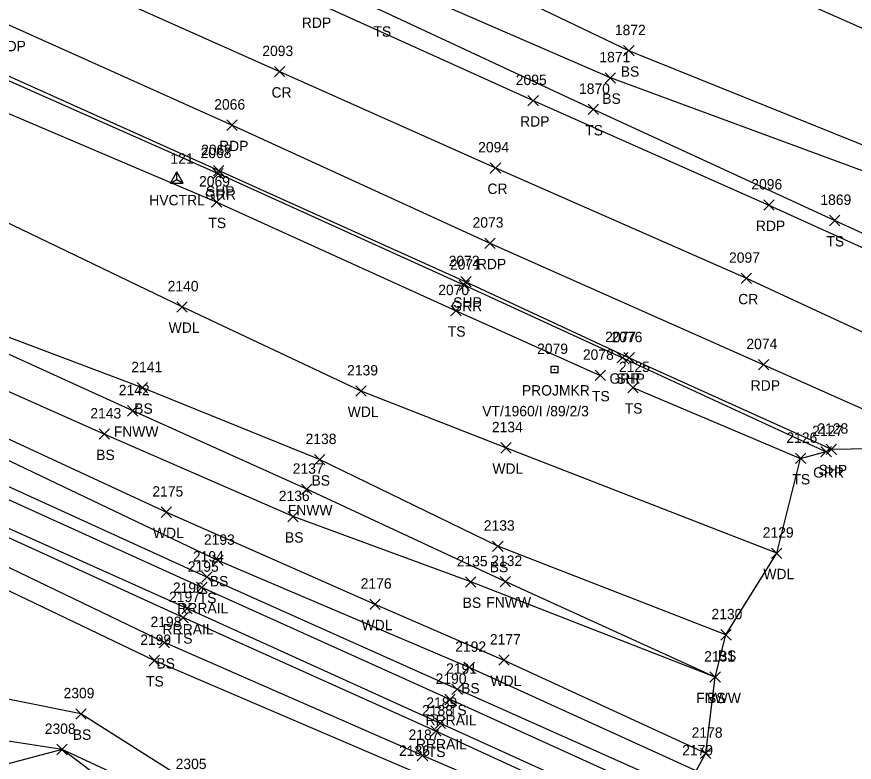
# Model space of a CAD drawing. Extents: x 1599569 to 1610055, y 642560 to 647860.
# Drawn here: x 1601651.7 to 1601812.9, y 647061.1 to 647204.6 of the extents above; entities that cross this region are included whole.
import ezdxf

# ---------------------------------------------------------------- set-up
doc = ezdxf.new("R2010")
doc.units = 0
for name, color, linetype in [('C_A', 7, 'Continuous'), ('C_I', 7, 'Continuous'), ('CPSM', 7, 'Continuous'), ('L_A', 7, 'Continuous'), ('L_I', 7, 'Continuous'), ('L_TIC', 7, 'Continuous'), ('LAWA', 7, 'Continuous'), ('LELB', 7, 'Continuous'), ('LFNC', 7, 'Continuous'), ('LSOGP', 7, 'Continuous'), ('P_A', 7, 'Continuous'), ('P_I', 7, 'Continuous'), ('P_TIC', 7, 'Continuous'), ('PET', 7, 'Continuous'), ('PRC', 7, 'Continuous'), ('PSP', 7, 'Continuous'), ('R_A', 7, 'Continuous'), ('R_I', 7, 'Continuous'), ('R_TIC', 7, 'Continuous'), ('RGR', 7, 'Continuous'), ('RR', 7, 'Continuous'), ('S_A', 7, 'Continuous'), ('S_C', 7, 'Continuous'), ('S_I', 7, 'Continuous'), ('SRM', 7, 'Continuous')]:
    doc.layers.add(name, color=color, linetype=linetype)

msp = doc.modelspace()

# ---------------------------------------------------------------- linework, layer by layer
at = {"layer": 'CPSM'}
for p, q in [((1601681.25, 647172.55), (1601682.5, 647174.72)), ((1601681.25, 647172.55), (1601682.5, 647173.27)), ((1601683.75, 647172.55), (1601682.5, 647174.72)), ((1601682.5, 647173.27), (1601682.5, 647174.72)), ((1601682.5, 647173.27), (1601682.5, 647173.27)), ((1601682.5, 647173.27), (1601683.75, 647172.55)), ((1601681.25, 647172.55), (1601683.75, 647172.55))]:
    msp.add_line(p, q, dxfattribs=at)
at = {"layer": 'L_TIC'}
for points in [[(1601768.5, 647197.02), (1601770.5, 647199.02)], [(1601770.5, 647197.02), (1601768.5, 647199.02)], [(1601764.95, 647191.8), (1601766.95, 647193.8)], [(1601766.95, 647191.8), (1601764.95, 647193.8)], [(1601761.69, 647185.72), (1601763.69, 647187.72)], [(1601763.69, 647185.72), (1601761.69, 647187.72)], [(1601689.17, 647167.89), (1601691.17, 647169.89)], [(1601691.17, 647167.89), (1601689.17, 647169.89)], [(1601808.11, 647164.35), (1601810.11, 647166.35)], [(1601810.11, 647164.35), (1601808.11, 647166.35)], [(1601682.51, 647147.72), (1601684.51, 647149.72)], [(1601684.51, 647147.72), (1601682.51, 647149.72)], [(1601735.24, 647146.99), (1601737.24, 647148.99)], [(1601737.24, 647146.99), (1601735.24, 647148.99)], [(1601762.99, 647134.54), (1601764.99, 647136.54)], [(1601764.99, 647134.54), (1601762.99, 647136.54)], [(1601674.86, 647132.15), (1601676.86, 647134.15)], [(1601676.86, 647132.15), (1601674.86, 647134.15)], [(1601716.97, 647131.53), (1601718.97, 647133.53)], [(1601718.97, 647131.53), (1601716.97, 647133.53)], [(1601769.29, 647132.19), (1601771.29, 647134.19)], [(1601771.29, 647132.19), (1601769.29, 647134.19)], [(1601673.01, 647127.72), (1601675.01, 647129.72)], [(1601675.01, 647127.72), (1601673.01, 647129.72)], [(1601667.54, 647123.24), (1601669.54, 647125.24)], [(1601669.54, 647123.24), (1601667.54, 647125.24)], [(1601744.83, 647120.59), (1601746.83, 647122.59)], [(1601746.83, 647120.59), (1601744.83, 647122.59)], [(1601708.97, 647118.32), (1601710.97, 647120.32)], [(1601710.97, 647118.32), (1601708.97, 647120.32)], [(1601801.57, 647118.55), (1601803.57, 647120.55)], [(1601803.57, 647118.55), (1601801.57, 647120.55)], [(1601706.5, 647112.61), (1601708.5, 647114.61)], [(1601708.5, 647112.61), (1601706.5, 647114.61)], [(1601679.48, 647108.21), (1601681.48, 647110.21)], [(1601681.48, 647108.21), (1601679.48, 647110.21)], [(1601703.87, 647107.35), (1601705.87, 647109.35)], [(1601705.87, 647107.35), (1601703.87, 647109.35)], [(1601743.28, 647101.65), (1601745.28, 647103.65)], [(1601745.28, 647101.65), (1601743.28, 647103.65)], [(1601689.4, 647098.93), (1601691.4, 647100.93)], [(1601691.4, 647098.93), (1601689.4, 647100.93)], [(1601796.97, 647100.31), (1601798.97, 647102.31)], [(1601798.97, 647100.31), (1601796.97, 647102.31)], [(1601687.29, 647095.71), (1601689.29, 647097.71)], [(1601689.29, 647095.71), (1601687.29, 647097.71)], [(1601738.06, 647094.78), (1601740.06, 647096.78)], [(1601740.06, 647094.78), (1601738.06, 647096.78)], [(1601744.72, 647094.86), (1601746.72, 647096.86)], [(1601746.72, 647094.86), (1601744.72, 647096.86)], [(1601719.64, 647090.49), (1601721.64, 647092.49)], [(1601721.64, 647090.49), (1601719.64, 647092.49)], [(1601682.7, 647087.91), (1601684.7, 647089.91)], [(1601684.7, 647087.91), (1601682.7, 647089.91)], [(1601787.18, 647084.6), (1601789.18, 647086.6)], [(1601789.18, 647084.6), (1601787.18, 647086.6)], [(1601679.12, 647083.11), (1601681.12, 647085.11)], [(1601681.12, 647083.11), (1601679.12, 647085.11)], [(1601677.16, 647079.66), (1601679.16, 647081.66)], [(1601679.16, 647079.66), (1601677.16, 647081.66)], [(1601744.45, 647079.74), (1601746.45, 647081.74)], [(1601746.45, 647079.74), (1601744.45, 647081.74)], [(1601737.77, 647078.33), (1601739.77, 647080.33)], [(1601739.77, 647078.33), (1601737.77, 647080.33)], [(1601785.11, 647076.46), (1601787.11, 647078.46)], [(1601787.11, 647076.46), (1601785.11, 647078.46)], [(1601785.11, 647076.46), (1601787.11, 647078.46)], [(1601787.11, 647076.46), (1601785.11, 647078.46)], [(1601735.46, 647074.12), (1601737.46, 647076.12)], [(1601737.46, 647074.12), (1601735.46, 647076.12)], [(1601663.03, 647069.39), (1601665.03, 647071.39)], [(1601665.03, 647069.39), (1601663.03, 647071.39)], [(1601731.38, 647066.08), (1601733.38, 647068.08)], [(1601733.38, 647066.08), (1601731.38, 647068.08)], [(1601659.42, 647062.53), (1601661.42, 647064.53)], [(1601661.42, 647062.53), (1601659.42, 647064.53)], [(1601659.42, 647062.53), (1601661.42, 647064.53)], [(1601661.42, 647062.53), (1601659.42, 647064.53)], [(1601783.29, 647061.8), (1601785.29, 647063.8)], [(1601785.29, 647061.8), (1601783.29, 647063.8)], [(1601728.79, 647061.38), (1601730.79, 647063.38)], [(1601730.79, 647061.38), (1601728.79, 647063.38)]]:
    msp.add_lwpolyline(points, dxfattribs=at)
at = {"layer": 'LAWA'}
for points in [[(1601797.97, 647101.31), (1601745.83, 647121.59), (1601717.97, 647132.53), (1601683.51, 647148.72), (1601645.76, 647166.92), (1601608.71, 647184.55), (1601562.01, 647202.4), (1601544.62, 647197.58)], [(1601522.66, 647190.03), (1601554.72, 647173.2), (1601590.69, 647150.24), (1601642.66, 647126.73), (1601680.48, 647109.21), (1601720.64, 647091.49), (1601745.45, 647080.74), (1601784.29, 647062.8)]]:
    msp.add_lwpolyline(points, dxfattribs=at)
at = {"layer": 'LELB'}
for points in [[(1601962.97, 647113.31), (1601923.69, 647130.08), (1601895.55, 647143.8), (1601852.73, 647162.89), (1601817.77, 647178.58), (1601769.5, 647198.02), (1601730.98, 647216.5), (1601688.1, 647233.1), (1601653.57, 647246.64), (1601608.27, 647265.53), (1601581.18, 647285.19)], [(1601782.46, 647059.4), (1601738.77, 647079.33), (1601690.4, 647099.93), (1601647.7, 647120.25), (1601610.06, 647137.74), (1601571.92, 647154.07), (1601536.97, 647170.25), (1601497.74, 647186.59), (1601465.75, 647201.27), (1601394.71, 647231.37), (1601362.21, 647245.73), (1601329.86, 647260.18), (1601292.61, 647278.06)], [(1601646.77, 647277.53), (1601686.47, 647261.15), (1601728.27, 647241.55), (1601783.31, 647216.16), (1601831.6, 647194.79), (1601880.63, 647172.23), (1601925.63, 647152.36), (1601972.37, 647131.79)], [(1601779.91, 647055.75), (1601736.46, 647075.12), (1601688.29, 647096.71), (1601645.48, 647116.21), (1601608.08, 647132.73), (1601569.65, 647149.89), (1601535.69, 647165.81), (1601496.65, 647183.57), (1601464.02, 647197.75), (1601393.37, 647229.99), (1601361.18, 647244.46), (1601329.08, 647258.95), (1601292.39, 647275.61)], [(1601775.59, 647047.17), (1601732.38, 647067.08), (1601683.7, 647088.91), (1601643.36, 647107.34), (1601603.44, 647124.91), (1601567.99, 647141.64), (1601531.27, 647157.66), (1601493.8, 647174.33), (1601459.44, 647189.9), (1601386.61, 647223.07), (1601358.08, 647235.63), (1601326.17, 647250.65), (1601291.06, 647266.1)], [(1601955.14, 647100.52), (1601918.75, 647116.38), (1601885.72, 647130.9), (1601846.21, 647148.37), (1601809.11, 647165.35), (1601762.69, 647186.72), (1601721.93, 647205.72), (1601682.69, 647222.55), (1601645.99, 647239.88), (1601604.12, 647258.19), (1601590.91, 647265.16)], [(1601773.31, 647043.55), (1601729.79, 647062.38), (1601680.12, 647084.11), (1601641.71, 647102.62), (1601602.29, 647120.48), (1601566.23, 647136.75), (1601528.31, 647153.55), (1601493.2, 647170.67), (1601457.65, 647186.55), (1601384.33, 647220.55), (1601356.62, 647233.9), (1601324.87, 647247.72), (1601290.33, 647262.4)], [(1601508.71, 647251.5), (1601538.21, 647237.23), (1601574.14, 647220.89), (1601606.18, 647207.34), (1601643.43, 647188.75), (1601690.17, 647168.89), (1601736.24, 647147.99), (1601763.99, 647135.54)], [(1601961.31, 647109.79), (1601923.17, 647125.81), (1601892.78, 647139.96), (1601850.81, 647159.82), (1601815.66, 647174.43), (1601765.95, 647192.8), (1601725.86, 647210.28), (1601688.1, 647233.1)], [(1601788.18, 647085.6), (1601744.28, 647102.65), (1601709.97, 647119.32), (1601675.86, 647133.15), (1601636.27, 647148.1), (1601596.45, 647168.4), (1601558.79, 647183.8), (1601537.2, 647194.37)], [(1601786.11, 647077.46), (1601739.06, 647095.78), (1601704.87, 647108.35), (1601668.54, 647124.24), (1601631.14, 647140.81), (1601590.66, 647159.56), (1601563.92, 647171), (1601557.22, 647179.13)], [(1601751.67, 647030.89), (1601730.47, 647037.42), (1601697.62, 647051.94), (1601683.46, 647052.81), (1601660.42, 647063.53), (1601634.93, 647067.43), (1601609.86, 647081.03), (1601579.64, 647095.5), (1601544.78, 647095.79), (1601527.55, 647075.32), (1601502.18, 647078.34), (1601460.45, 647090.07), (1601427.5, 647095.12), (1601380.72, 647086.4), (1601347.8, 647085.38), (1601322.34, 647094.84), (1601293.67, 647118.34), (1601268.03, 647147.72), (1601257.75, 647175.7)], [(1601786.42, 647020.74), (1601762.67, 647028.99), (1601751.67, 647030.89), (1601732.96, 647040.23), (1601698.47, 647053.93), (1601685.61, 647056.76), (1601664.03, 647070.39), (1601639.36, 647075.33), (1601612.31, 647092.93), (1601584.19, 647104.61), (1601538.73, 647126.26), (1601520.13, 647131.26), (1601491.52, 647137.58), (1601474.1, 647124.14), (1601450.02, 647123.17), (1601433.67, 647131.14), (1601416.15, 647122.17), (1601393.03, 647131.84), (1601363.94, 647128.32), (1601336.7, 647135.49), (1601311.97, 647149.61), (1601287.9, 647169.52)], [(1601770.94, 647039.49), (1601728.02, 647059.31), (1601678.16, 647080.66), (1601639.64, 647099.09), (1601600.86, 647116.76), (1601564.63, 647133.02), (1601543.96, 647141.4)], [(1601770.29, 647133.19), (1601802.57, 647119.55)], [(1601762.67, 647028.99), (1601750.87, 647021.59), (1601728.34, 647036), (1601697.16, 647048.99), (1601679.27, 647049.33), (1601660.42, 647063.53), (1601632.57, 647056.16), (1601605.11, 647066.7), (1601577.38, 647081.92), (1601557.99, 647089.73)]]:
    msp.add_lwpolyline(points, dxfattribs=at)
at = {"layer": 'LFNC'}
msp.add_lwpolyline([(1601786.11, 647077.46), (1601745.72, 647095.86), (1601707.5, 647113.61), (1601674.01, 647128.72), (1601634.94, 647146.46), (1601593.54, 647164.14), (1601557.22, 647179.13), (1601524.27, 647193.83)], dxfattribs=at)
at = {"layer": 'LSOGP'}
msp.add_lwpolyline([(1601782.46, 647059.4), (1601784.29, 647062.81), (1601786.11, 647077.47), (1601788.18, 647085.61), (1601797.97, 647101.31), (1601802.57, 647119.55), (1601807.48, 647120.86), (1601808.48, 647121.33), (1601831.12, 647121.72), (1601838.26, 647118.54), (1601845.39, 647115.36), (1601852.52, 647112.19), (1601874.76, 647116.71), (1601912.89, 647115.64), (1601955.15, 647100.52)], dxfattribs=at)
at = {"layer": 'P_TIC'}
for points in [[(1601701.28, 647193), (1601703.28, 647195)], [(1601703.28, 647193), (1601701.28, 647195)], [(1601750.08, 647187.42), (1601752.08, 647189.42)], [(1601752.08, 647187.42), (1601750.08, 647189.42)], [(1601692.14, 647182.7), (1601694.14, 647184.7)], [(1601694.14, 647182.7), (1601692.14, 647184.7)], [(1601689.56, 647173.95), (1601691.56, 647175.95)], [(1601691.56, 647173.95), (1601689.56, 647175.95)], [(1601742.84, 647174.46), (1601744.84, 647176.46)], [(1601744.84, 647174.46), (1601742.84, 647176.46)], [(1601795.47, 647167.32), (1601797.47, 647169.32)], [(1601797.47, 647167.32), (1601795.47, 647169.32)], [(1601741.76, 647159.97), (1601743.76, 647161.97)], [(1601743.76, 647159.97), (1601741.76, 647161.97)], [(1601737.15, 647152.57), (1601739.15, 647154.57)], [(1601739.15, 647152.57), (1601737.15, 647154.57)], [(1601791.12, 647153.22), (1601793.12, 647155.22)], [(1601793.12, 647153.22), (1601791.12, 647155.22)], [(1601768.56, 647137.92), (1601770.56, 647139.92)], [(1601770.56, 647137.92), (1601768.56, 647139.92)], [(1601794.46, 647136.6), (1601796.46, 647138.6)], [(1601796.46, 647136.6), (1601794.46, 647138.6)], [(1601807.48, 647120.32), (1601809.48, 647122.32)], [(1601809.48, 647120.32), (1601807.48, 647122.32)]]:
    msp.add_lwpolyline(points, dxfattribs=at)
at = {"layer": 'PET'}
for points in [[(1601331.98, 647346.68), (1601356.59, 647335.73), (1601398.36, 647316.98), (1601437.48, 647298.89), (1601470.99, 647284.11), (1601510.02, 647266.15), (1601543.75, 647251.34), (1601580.52, 647234.21), (1601606.39, 647222.8), (1601650.31, 647202.92), (1601693.14, 647183.7), (1601742.76, 647160.97), (1601795.46, 647137.6), (1601852.51, 647112.19)], [(1601401.84, 647345.99), (1601436.76, 647329.85), (1601477.89, 647310.69), (1601511.69, 647295.64), (1601529.2, 647287.58), (1601568.21, 647270.13), (1601613.57, 647249.46), (1601666.31, 647226.36), (1601709.07, 647207.41), (1601751.08, 647188.42), (1601796.47, 647168.32), (1601839.63, 647148.76), (1601881.89, 647129.58), (1601912.89, 647115.63)]]:
    msp.add_lwpolyline(points, dxfattribs=at)
at = {"layer": 'PRC'}
msp.add_lwpolyline([(1601345.39, 647355.71), (1601383.98, 647338.31), (1601428.29, 647317.74), (1601472.83, 647297.09), (1601504.71, 647281.99), (1601534.71, 647269.01), (1601561.28, 647257.19), (1601605.65, 647237.34), (1601658.4, 647213.63), (1601702.28, 647194), (1601743.84, 647175.46), (1601792.12, 647154.22), (1601833.09, 647135.23), (1601874.76, 647116.71)], dxfattribs=at)
at = {"layer": 'PSP'}
msp.add_lwpolyline([(1601320.4, 647342.24), (1601352.25, 647327.85), (1601395.49, 647308.51), (1601432.16, 647291.56), (1601467.04, 647275.92), (1601506.79, 647257.96), (1601540.92, 647242.41), (1601577, 647226.25), (1601607.65, 647212.12), (1601646.7, 647194.68), (1601690.56, 647174.95), (1601738.15, 647153.57), (1601769.56, 647138.92), (1601808.48, 647121.32)], dxfattribs=at)
at = {"layer": 'R_TIC'}
for points in [[(1601689.44, 647173.37), (1601691.44, 647175.37)], [(1601691.44, 647173.37), (1601689.44, 647175.37)], [(1601736.84, 647151.88), (1601738.84, 647153.88)], [(1601738.84, 647151.88), (1601736.84, 647153.88)], [(1601767.28, 647137.94), (1601769.28, 647139.94)], [(1601769.28, 647137.94), (1601767.28, 647139.94)], [(1601806.48, 647119.85), (1601808.48, 647121.85)], [(1601808.48, 647119.85), (1601806.48, 647121.85)], [(1601686.31, 647093.74), (1601688.31, 647095.74)], [(1601688.31, 647093.74), (1601686.31, 647095.74)], [(1601683.48, 647089.67), (1601685.48, 647091.67)], [(1601685.48, 647089.67), (1601683.48, 647091.67)], [(1601734.09, 647072.16), (1601736.09, 647074.16)], [(1601736.09, 647072.16), (1601734.09, 647074.16)], [(1601732.22, 647067.55), (1601734.22, 647069.55)], [(1601734.22, 647067.55), (1601732.22, 647069.55)]]:
    msp.add_lwpolyline(points, dxfattribs=at)
at = {"layer": 'RGR'}
msp.add_lwpolyline([(1601318.76, 647342.22), (1601351.89, 647327.35), (1601395.14, 647307.81), (1601432.06, 647291.1), (1601467.03, 647275.18), (1601506.65, 647256.87), (1601540.97, 647241.89), (1601576.91, 647225.43), (1601607.45, 647211.71), (1601646.25, 647193.96), (1601690.44, 647174.37), (1601737.84, 647152.88), (1601768.28, 647138.94), (1601807.48, 647120.85)], dxfattribs=at)
at = {"layer": 'RR'}
for points in [[(1601779.12, 647053.17), (1601735.09, 647073.16), (1601687.31, 647094.74), (1601644.71, 647114), (1601606.95, 647130.88), (1601569.09, 647148.12), (1601534.47, 647163.75), (1601495.86, 647181.28), (1601463.02, 647196.09), (1601391.8, 647228.12), (1601360.22, 647242.53), (1601328.26, 647256.93), (1601292.48, 647273.14)], [(1601776.78, 647048.8), (1601733.22, 647068.55), (1601684.48, 647090.67), (1601642.81, 647109.31), (1601604.47, 647126.66), (1601567.91, 647143.17), (1601532.13, 647159.27), (1601494.47, 647176.35), (1601460.57, 647191.75), (1601388.17, 647224.38), (1601357.5, 647238.3), (1601326.5, 647252.29), (1601291.28, 647268.22)]]:
    msp.add_lwpolyline(points, dxfattribs=at)
at = {"layer": 'SRM'}
msp.add_lwpolyline([(1601754.56, 647137.28), (1601755.81, 647137.28), (1601755.81, 647136.03), (1601754.56, 647136.03)], close=True, dxfattribs=at)
msp.add_circle((1601755.19, 647136.66), 0.0833, dxfattribs=at)

# ---------------------------------------------------------------- texts
at = {"layer": 'C_A'}
msp.add_text('HVCTRL', height=2, dxfattribs=at).set_placement((1601677.19, 647168.27))
at = {"layer": 'C_I'}
msp.add_text('121', height=2, dxfattribs=at).set_placement((1601681.27, 647176.27))
at = {"layer": 'L_A'}
for s, p in [('TS', (1601720.34, 647200.72)), ('BS', (1601767.94, 647193.02)), ('BS', (1601764.39, 647187.8)), ('TS', (1601761.1, 647181.72)), ('TS', (1601688.57, 647163.89)), ('TS', (1601807.52, 647160.35)), ('WDL', (1601680.93, 647143.72)), ('TS', (1601734.65, 647142.99)), ('TS', (1601762.4, 647130.54)), ('BS', (1601674.3, 647128.15)), ('TS', (1601768.7, 647128.19)), ('WDL', (1601715.39, 647127.53)), ('FNWW', (1601670.36, 647123.72)), ('BS', (1601666.98, 647119.24)), ('WDL', (1601743.24, 647116.59)), ('BS', (1601708.41, 647114.32)), ('TS', (1601800.98, 647114.55)), ('FNWW', (1601703.85, 647108.61)), ('WDL', (1601677.9, 647104.21)), ('BS', (1601703.31, 647103.35)), ('BS', (1601742.72, 647097.65)), ('WDL', (1601795.39, 647096.31)), ('BS', (1601688.84, 647094.93)), ('TS', (1601686.7, 647091.71)), ('BS', (1601737.51, 647090.78)), ('FNWW', (1601742.06, 647090.86)), ('WDL', (1601718.06, 647086.49)), ('TS', (1601682.1, 647083.91)), ('BS', (1601786.62, 647080.6)), ('BS', (1601678.56, 647079.11)), ('TS', (1601676.57, 647075.66)), ('WDL', (1601742.86, 647075.74)), ('BS', (1601737.22, 647074.33)), ('FNWW', (1601782.46, 647072.46)), ('BS', (1601784.55, 647072.46)), ('TS', (1601734.87, 647070.12)), ('BS', (1601662.47, 647065.39)), ('TS', (1601730.79, 647062.08))]:
    msp.add_text(s, height=2, dxfattribs=at).set_placement(p)
at = {"layer": 'L_I'}
for s, p in [('1872', (1601766.81, 647201.02)), ('1871', (1601763.83, 647195.8)), ('1870', (1601759.91, 647189.72)), ('2069', (1601686.77, 647171.89)), ('1869', (1601806.36, 647168.35)), ('2140', (1601680.73, 647151.72)), ('2070', (1601732.81, 647150.99)), ('2078', (1601760.65, 647138.54)), ('2141', (1601673.74, 647136.15)), ('2125', (1601767.6, 647136.19)), ('2139', (1601715.27, 647135.53)), ('2142', (1601671.32, 647131.72)), ('2143', (1601665.85, 647127.24)), ('2134', (1601743.13, 647124.59)), ('2138', (1601707.28, 647122.32)), ('2126', (1601799.82, 647122.55)), ('2137', (1601704.81, 647116.61)), ('2175', (1601677.79, 647112.21)), ('2136', (1601702.12, 647111.35)), ('2133', (1601741.58, 647105.65)), ('2129', (1601795.27, 647104.31)), ('2193', (1601687.71, 647102.93)), ('2194', (1601685.59, 647099.71)), ('2135', (1601736.37, 647098.78)), ('2132', (1601743.02, 647098.86)), ('2176', (1601717.89, 647094.49)), ('2197', (1601681, 647091.91)), ('2130', (1601785.4, 647088.6)), ('2198', (1601677.43, 647087.11)), ('2199', (1601675.46, 647083.66)), ('2177', (1601742.75, 647083.74)), ('2192', (1601736.08, 647082.33)), ('2131', (1601783.99, 647080.46)), ('2131', (1601783.99, 647080.46)), ('2191', (1601734.33, 647078.12)), ('2309', (1601660.69, 647073.39)), ('2188', (1601729.69, 647070.08)), ('2308', (1601657.08, 647066.53)), ('2308', (1601657.08, 647066.53)), ('2187', (1601727.1, 647065.38)), ('2178', (1601781.59, 647065.8)), ('2186', (1601725.27, 647062.31)), ('2179', (1601779.76, 647062.4)), ('2305', (1601682.27, 647059.76))]:
    msp.add_text(s, height=2, dxfattribs=at).set_placement(p)
at = {"layer": 'P_A'}
for s, p in [('RDP', (1601706.56, 647202.41)), ('RDP', (1601647.8, 647197.92)), ('CR', (1601700.72, 647189)), ('RDP', (1601748.57, 647183.42)), ('RDP', (1601690.63, 647178.7)), ('SHP', (1601688.09, 647169.95)), ('CR', (1601742.28, 647170.46)), ('RDP', (1601793.95, 647163.32)), ('RDP', (1601740.25, 647155.97)), ('CR', (1601790.55, 647149.22)), ('SHP', (1601735.69, 647148.57)), ('SHP', (1601767.09, 647133.92)), ('RDP', (1601792.95, 647132.6)), ('SHP', (1601806.01, 647116.32))]:
    msp.add_text(s, height=2, dxfattribs=at).set_placement(p)
at = {"layer": 'P_I'}
for s, p in [('2093', (1601698.95, 647197)), ('2095', (1601747.74, 647191.42)), ('2066', (1601689.7, 647186.7)), ('2067', (1601687.17, 647177.95)), ('2094', (1601740.5, 647178.46)), ('2096', (1601793.07, 647171.32)), ('2073', (1601739.42, 647163.97)), ('2097', (1601788.78, 647157.22)), ('2072', (1601734.82, 647156.57)), ('2076', (1601766.16, 647141.92)), ('2074', (1601792.12, 647140.6)), ('2128', (1601805.78, 647124.32))]:
    msp.add_text(s, height=2, dxfattribs=at).set_placement(p)
at = {"layer": 'R_A'}
for s, p in [('GRR', (1601687.93, 647169.37)), ('GRR', (1601735.33, 647147.88)), ('GRR', (1601765.77, 647133.94)), ('GRR', (1601804.97, 647115.85)), ('RRRAIL', (1601682.6, 647089.74)), ('RRRAIL', (1601679.77, 647085.67)), ('RRRAIL', (1601730.38, 647068.16)), ('RRRAIL', (1601728.52, 647063.55))]:
    msp.add_text(s, height=2, dxfattribs=at).set_placement(p)
at = {"layer": 'R_I'}
for s, p in [('2068', (1601687.06, 647177.37)), ('2071', (1601735.07, 647155.88)), ('2077', (1601764.94, 647141.94)), ('2127', (1601804.79, 647123.85)), ('2195', (1601684.61, 647097.74)), ('2196', (1601681.74, 647093.67)), ('2190', (1601732.31, 647076.16)), ('2189', (1601730.52, 647071.55))]:
    msp.add_text(s, height=2, dxfattribs=at).set_placement(p)
at = {"layer": 'S_A'}
msp.add_text('PROJMKR', height=2, dxfattribs=at).set_placement((1601748.91, 647131.66))
at = {"layer": 'S_C'}
msp.add_text('VT/1960/I /89/2/3', height=2, dxfattribs=at).set_placement((1601741.28, 647127.66))
at = {"layer": 'S_I'}
msp.add_text('2079', height=2, dxfattribs=at).set_placement((1601751.84, 647139.66))

doc.saveas('drawing.dxf')
